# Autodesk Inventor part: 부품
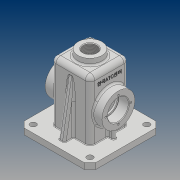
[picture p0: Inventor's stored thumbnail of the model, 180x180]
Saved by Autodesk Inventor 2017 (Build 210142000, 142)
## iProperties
Part Number: 부품
Material: 일반
Document SubType Name: Modeling
Designer: 20
Density: 1 g/cm^3
Appearance: 기본값
Author: 20
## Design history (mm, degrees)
sketch "스케치1"
  geometry: L1 (-32.5, 32.5)-(32.5, 32.5); L2 (32.5, 32.5)-(32.5, -32.5); L3 (32.5, -32.5)-(-32.5, -32.5); L4 (-32.5, -32.5)-(-32.5, 32.5); L5 (-32.5, 32.5)-(32.5, -32.5); L6 (32.5, 32.5)-(-32.5, -32.5); 1 further point
  constraints: 12 end point, 2 midpoint, 2 parallel, 1 horizontal, 1 perpendicular
  dimensions: "d0" = 65 distance of L2.end L3.end; "d1" = 65 distance of L1.end L2.end
extrude "돌출1" new body sketch "스케치1" distance "d2" = 110; taper "d3" = 0 deg
fillet "모깎기1" dims "d4" = 8
fillet "모깎기2" dims "d5" = 8
sketch "스케치2"
  geometry: L1 (-60, -60)-(60, -60); L2 (60, -60)-(60, 60); L3 (60, 60)-(-60, 60); L4 (-60, 60)-(-60, -60); L5 (-60, -60)-(60, 60); L6 (60, -60)-(-60, 60); L7 (24.5, 32.5)-(-24.5, 32.5) reference; L8 (-32.5, 24.5)-(-32.5, -24.5) reference; L9 (-24.5, -32.5)-(24.5, -32.5) reference; L10 (32.5, -24.5)-(32.5, 24.5) reference; A1 r 8 centre (24.5, 24.5) between (32.5, 24.5) and (24.5, 32.5) reference; A2 r 8 centre (-24.5, 24.5) between (-24.5, 32.5) and (-32.5, 24.5) reference; A3 r 8 centre (-24.5, -24.5) between (-32.5, -24.5) and (-24.5, -32.5) reference; A4 r 8 centre (24.5, -24.5) between (24.5, -32.5) and (32.5, -24.5) reference; 1 further point
  constraints: 12 end point, 2 midpoint, 2 parallel, 1 horizontal, 1 perpendicular
  dimensions: "d7" = 120 distance of L3.end L2.end; "d8" = 120 distance of L1.end L2.end
extrude "돌출2" join sketch "스케치2" distance "d9" = 10; taper "d10" = 0 deg
chamfer "모따기1" distance "d11" = 10; stored, may be unused: second distance "d12" = 2, angle "d13" = 45 deg
sketch "스케치3"
  geometry: L1 (102, 74.5)-(102, -25.5) reference; C1 r 27.5 at (47, 24.5); 2 further points
  constraints: 1 centre point, 1 horizontal alignment, 1 midpoint
  dimensions: "d14" = 55 diameter of C1; "d15" = 55 distance from line of L1 C1.centre
extrude "돌출3" join sketch "스케치3" distance "d16" = 15; taper "d17" = 0 deg
sketch "스케치4"
  geometry: L1 (55, 50)-(55, -50) reference; 3 further points
  constraints: 1 horizontal alignment, 1 midpoint
  dimensions: "d18" = 76 distance from line of L1 point (-21, 0)
hole "구멍1" sketch "스케치4" at (-21, 0) diameter "d19" = 3.242; stored, may be unused: countersink angle "d23" = 90 deg, drill point angle "d25" = 118 deg; dims "d20" = 8, "d21" = 4, "d22" = 2, "d24" = 10
sketch "스케치5"
  geometry: C1 r 15 at (0, 0); A1 r 27.5 centre (0, 0) between (-12.49, 24.5) and (-12.49, -24.5) reference; 1 further point
  constraints: 1 centre point, 1 coincident
  dimensions: "d29" = 30 diameter of C1
extrude "돌출4" cut sketch "스케치5" stored distance "d30" = 15; taper "d31" = 0 deg
sketch "스케치7"
  geometry: C1 r 20 at (0, 0); 1 further point
  constraints: 1 centre point, 1 coincident
  dimensions: "d35" = 40 diameter of C1
extrude "돌출6" join sketch "스케치7" distance "d36" = 10; taper "d37" = 0 deg
hole "구멍2" diameter "d41" = 22.835; stored, may be unused: countersink angle "d45" = 90 deg, drill point angle "d47" = 118 deg; dims "d39" = 10, "d40" = 10, "d42" = 50, "d43" = 4, "d44" = 2, "d46" = 59.3
sketch "스케치10"
  geometry: L1 (-27.5, -27.5)-(27.5, -27.5); L2 (27.5, -27.5)-(27.5, 27.5); L3 (27.5, 27.5)-(-27.5, 27.5); L4 (-27.5, 27.5)-(-27.5, -27.5); L5 (-27.5, -27.5)-(27.5, 27.5); L6 (27.5, -27.5)-(-27.5, 27.5); 1 further point
  constraints: 12 end point, 2 midpoint, 2 parallel, 1 horizontal, 1 perpendicular
  dimensions: "d50" = 55 distance of L3.end L2.end; "d51" = 55 distance of L1.end L2.end
extrude "돌출7" cut sketch "스케치10" distance "d52" = 105; taper "d53" = 0 deg
fillet "모깎기3" dims "d54" = 3
fillet "모깎기4" dims "d55" = 3
sketch "스케치11"
  geometry: C1 r 15 at (0, 0) reference; C2 r 17.5 at (0, 0); 1 further point
  constraints: 1 centre point, 1 coincident
  dimensions: "d56" = 35 diameter of C2
extrude "돌출8" cut sketch "스케치11" distance "d57" = 17; taper "d58" = 0 deg
sketch "스케치14"
  geometry: L1 (50, 10)-(-50, 10) reference; L2 (-32.5, 10)-(-32.5, 102) reference; L3 (-48, 10)-(-32.5, 97.905); L4 (-60, 0)-(-60, 10) reference; 1 further point
  constraints: 2 end point, 2 point on line
  dimensions: "d59" = 12 distance from line of L4 L3.start; "d60" = 10 deg angle of L4 L3
feature "리브1" sketch "스케치14" dims "d61" = 1, "d62" = 10, "d63" = 0, "d64" = 0, "d65" = 1, "d66" = 1
sketch "스케치15"
  geometry: L1 (32.5, 3)-(42.5, 3); L2 (42.5, 3)-(42.5, -3); L3 (42.5, -3)-(32.5, -3); L4 (32.5, -3)-(32.5, 3); L5 (32.5, -24.5)-(32.5, 24.5) reference; 2 further points
  constraints: 8 end point, 2 parallel, 1 collinear, 1 horizontal, 1 midpoint, 1 perpendicular
  dimensions: "d74" = 6 distance of L1.end L2.end; "d75" = 3 distance from line of point (0, 0) L1; "d76" = 42.5 distance from line of L2 point (0, 0)
extrude "돌출9" join sketch "스케치15" stored distance "d77" = 17; taper "d78" = 0 deg
sketch "스케치16"
  geometry: C1 r 5 at (47.5, 47.5); 1 further point
  constraints: 1 centre point
  dimensions: "d79" = 10 diameter of C1; "d80" = 47.5 horizontal distance of C1.centre point (0, 0); "d81" = 47.5 horizontal distance of C1.centre point (0, 0)
extrude "돌출10" cut sketch "스케치16" stored distance "d82" = 17; taper "d83" = 0 deg
fillet "모깎기5" dims "d90" = 0.3
chamfer "모따기2" distance "d91" = 1; stored, may be unused: second distance "d92" = 2, angle "d93" = 45 deg
fillet "모깎기7" dims "d95" = 3
fillet "모깎기8" dims "d96" = 3
fillet "모깎기9" dims "d97" = 3
fillet "모깎기10" dims "d98" = 3
fillet "모깎기12" dims "d100" = 1
node "작업 평면1"
sketch "스케치17"
  geometry: L1 (-18, 44.5)-(-18, 4.5) reference; L2 (0, -8)-(91, -8) reference; 2 further points
  constraints: 1 other
  dimensions: "d103" = 26 distance from line of point (8, 24.5) L1; "d104" = 32.5 distance from line of L2 point (8, 24.5)
feature "엠보싱1" sketch "스케치17" dims "d7" = 120, "d8" = 120, "d105" = 0.5, "d106" = 0
fillet "모깎기14" dims "d107" = 3
feature "면 기울기2" dims angle "d108" = 5 deg
fillet "모깎기15" dims "d109" = 3
node "솔리드1"
pattern_circular "원형 패턴1" dims angle "d27" = 360 deg
mirror "미러1"
mirror "미러3"
mirror "미러4"
mirror "미러5"
pattern_linear "직사각형 패턴1" dims "d86" = 95, "d89" = 95
node "투영된 루프1"
